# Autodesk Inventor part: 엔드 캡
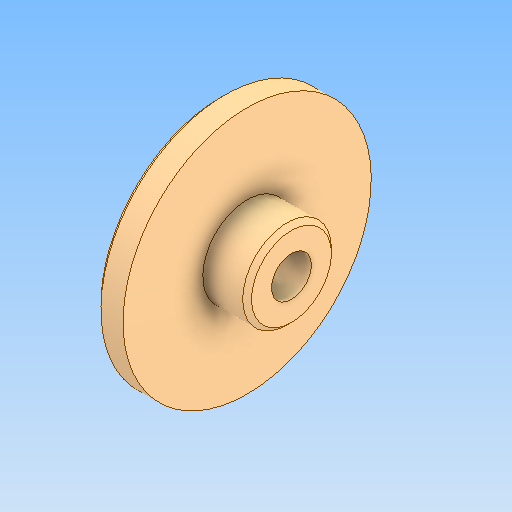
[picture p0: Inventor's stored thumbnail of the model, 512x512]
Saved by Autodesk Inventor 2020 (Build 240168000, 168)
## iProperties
Created: 2025-11
Part Number: 엔드 캡
Material: 강철, 연강
Document SubType Name: Modeling
Designer: PC2-06
Density: 7.85 g/cm^3
Appearance: 기본값
Author: jhkim
Sending System: Autodesk Inventor 2026
Preprocessor: ST-DEVELOPER v20.1
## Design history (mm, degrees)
feature "솔리드1"
node "솔리드2"
